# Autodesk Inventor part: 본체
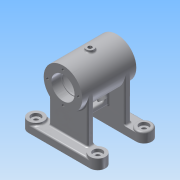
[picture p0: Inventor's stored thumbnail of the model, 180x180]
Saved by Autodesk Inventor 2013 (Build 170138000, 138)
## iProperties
Created: 2015-11
Part Number: 본체
Material: 알루미늄 6061
Document SubType Name: Modeling
Designer: Administrator
Density: 2.71 g/cm^3
Mass: 362.822 g
Surface Area: 463.591 cm^2
Volume: 133.883 cm^3
Author: Administrator
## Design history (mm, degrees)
sketch "스케치1"
  geometry: 1 further point
sketch "스케치2"
  geometry: L1 (0, 40)-(-40, 40); L2 (-40, 40)-(-40, 30); L3 (-40, 20)-(40, 20); L4 (40, 20)-(40, 30); L5 (40, 40)-(0, 40); L6 (0, -40)-(-40, -40); L7 (-40, -40)-(-40, -30); L8 (-40, -20)-(40, -20); L9 (40, -20)-(40, -30); L10 (40, -40)-(0, -40); A1 r 10 centre (-40, 30) between (-40, 40) and (-40, 20); A2 r 10 centre (40, 30) between (40, 20) and (40, 40); A3 r 10 centre (-40, -30) between (-40, -20) and (-40, -40); A4 r 10 centre (40, -30) between (40, -40) and (40, -20)
  constraints: 20 end point, 8 point on circle, 4 centre point, 4 coincident, 2 perpendicular, 2 tangent
  dimensions: "d9" = 40 distance of L1.start L1.end; "d10" = 10 distance of L1.end L2.end; "d11" = 80 distance of L3.start L3.end; "d12" = 10 distance of L3.end L4.end
extrude "돌출1" new body sketch "스케치2" distance "d13" = 10; taper "d14" = 0 deg
node "작업 평면1"
sketch "스케치3"
  geometry: L1 (40, 20)-(-40, 20) reference; L2 (-40, 40)-(40, 40) reference; L3 (-40, -20)-(40, -20) reference; L4 (40, -40)-(-40, -40) reference; C1 r 10 at (-40, 30); A1 r 10 centre (40, 30) between (40, 20) and (40, 40) reference; A2 r 10 centre (-40, 30) between (-40, 40) and (-40, 20) reference; A3 r 10 centre (-40, -30) between (-40, -20) and (-40, -40) reference; A4 r 10 centre (40, -30) between (40, -40) and (40, -20) reference; 4 further points
  constraints: 4 coincident, 3 vertical alignment, 1 centre point, 6 other
  dimensions: "d16" = 20 diameter of C1
extrude "돌출2" join sketch "스케치3" distance "d17" = 3; taper "d18" = 0 deg
sketch "스케치4"
  geometry: L1 (-40, -20)-(40, -20) reference; L2 (40, -40)-(-40, -40) reference; L3 (-40, 40)-(40, 40) reference; L4 (40, 20)-(-40, 20) reference; L5 (0, -20)-(-25, -20); L6 (-25, -20)-(-25, -28); L7 (-25, -28)-(25, -28); L8 (25, -28)-(25, -20); A1 r 10 centre (-40, -30) between (-40, -40) and (-40, -20) reference; A2 r 10 centre (-40, -30) between (-40, -20) and (-40, -40) reference; A3 r 10 centre (40, -30) between (40, -40) and (40, -20) reference; A4 r 10 centre (40, -30) between (40, -20) and (40, -40) reference; A5 r 10 centre (40, 30) between (40, 20) and (40, 40) reference; A6 r 10 centre (40, 30) between (40, 40) and (40, 20) reference; A7 r 10 centre (-40, 30) between (-40, 40) and (-40, 20) reference; A8 r 10 centre (-40, 30) between (-40, 20) and (-40, 40) reference; 1 further point
  constraints: 8 end point, 2 perpendicular, 2 point on line, 1 midpoint, 1 parallel
  dimensions: "d19" = 25 distance of L5.start L5.end; "d20" = 8 distance of L5.end L6.end; "d21" = 50 distance of L6.end L7.end
extrude "돌출3" join sketch "스케치4" distance "d22" = 58; taper "d23" = 0 deg
sketch "스케치5"
  geometry: L1 (0, 0)-(0, 68); C1 r 25 at (0, 68)
  constraints: 2 end point, 1 centre point, 1 coincident, 1 vertical
  dimensions: "d24" = 68 distance of L1.start L1.end; "d25" = 50 diameter of C1
extrude "돌출4" join sketch "스케치5" stored distance "d26" = 70; taper "d27" = 0 deg
node "작업 평면3"
sketch "스케치6"
  geometry: L1 (-25, 28)-(25, 28) reference; L2 (25, 28)-(25, 20) reference; L3 (25, 20)-(-25, 20) reference; L4 (-25, 20)-(-25, 28) reference; L5 (-25, -20)-(25, -20) reference; L6 (25, -20)-(25, -28) reference; L7 (25, -28)-(-25, -28) reference; L8 (-25, -28)-(-25, -20) reference; L9 (-25, 28)-(25, 28) reference; L10 (25, 28)-(25, 20) reference; L11 (25, 20)-(-25, 20) reference; L12 (-25, 20)-(-25, 28) reference; L13 (-25, -20)-(25, -20) reference; L14 (25, -20)-(25, -28) reference; L15 (25, -28)-(-25, -28) reference; L16 (-25, -28)-(-25, -20) reference; L17 (0, 20)-(-4, 20); L18 (-4, 20)-(-4, -20); L19 (-4, -20)-(4, -20); L20 (4, -20)-(4, 20); L21 (4, 20)-(0, 20); 1 further point
  constraints: 10 end point, 4 point on line, 2 perpendicular, 1 collinear, 1 midpoint
  dimensions: "d30" = 8 distance of L18.end L19.end
extrude "돌출5" join sketch "스케치6" stored distance "d31" = 70; taper "d32" = 0 deg
sketch "스케치7"
  geometry: L1 (-13.5, 8.5)-(-13.5, 31.5); L2 (-6.5, 31.5)-(-6.5, 8.5); A1 r 3.5 centre (-10, 31.5) between (-6.5, 31.5) and (-13.5, 31.5); A2 r 3.5 centre (-10, 8.5) between (-13.5, 8.5) and (-6.5, 8.5); 1 further point
  constraints: 4 end point, 4 point on circle, 3 tangent, 2 centre point, 1 parallel
  dimensions: "d35" = 7 diameter of A1; "d37" = 7 diameter of A2
extrude "돌출6" cut sketch "스케치7" distance "d38" = 70; taper "d39" = 0 deg
node "작업 평면7"
sketch "스케치8"
  geometry: C1 r 5 at (0, 0); 1 further point
  constraints: 1 centre point, 1 coincident
  dimensions: "d41" = 10 diameter of C1
extrude "돌출7" join sketch "스케치8" stored distance "d42" = 70; taper "d43" = 0 deg
hole "구멍2" diameter "d55" = 30; stored, may be unused: countersink angle "d59" = 90 deg, drill point angle "d61" = 0 deg; dims "d53" = 10, "d54" = 10, "d56" = 6, "d57" = 4, "d58" = 2, "d60" = 12
hole "구멍3" diameter "d64" = 30; stored, may be unused: countersink angle "d68" = 90 deg, drill point angle "d70" = 0 deg; dims "d62" = 10, "d63" = 10, "d65" = 6, "d66" = 4, "d67" = 2, "d69" = 12
sketch "스케치9"
  geometry: C1 r 14 at (0, 0); 1 further point
  constraints: 1 centre point
  dimensions: "d71" = 28 diameter of C1
extrude "돌출8" cut sketch "스케치9" distance "d72" = 2; taper "d73" = 0 deg
sketch "스케치10"
  geometry: C1 r 14 at (0, 0); 1 further point
  constraints: 1 centre point
  dimensions: "d74" = 28 diameter of C1
extrude "돌출9" cut sketch "스케치10" distance "d75" = 2; taper "d76" = 0 deg
sketch "스케치11"
  geometry: C1 r 21 at (0, 0); 1 further point
  constraints: 1 centre point
  dimensions: "d77" = 42 diameter of C1
extrude "돌출10" cut sketch "스케치11" distance "d78" = 42; taper "d79" = 0 deg
hole "구멍4" diameter "d82" = 4.917; stored, may be unused: countersink angle "d86" = 90 deg, drill point angle "d88" = 0 deg; dims "d80" = 10, "d81" = 10, "d83" = 6, "d84" = 4, "d85" = 2, "d87" = 20
sketch "스케치12"
  geometry: 2 further points
hole "구멍6" sketch "스케치12" at (0, 20) diameter "d102" = 3.242; stored, may be unused: countersink angle "d106" = 82 deg, drill point angle "d108" = 118 deg; dims "d103" = 8, "d104" = 3.023, "d105" = 2, "d107" = 10
node "작업 평면8"
sketch "스케치13"
  geometry: 1 further point
sketch "스케치14"
  geometry: L1 (81.881, 40.033)-(81.881, 16.238); L2 (81.881, 16.238)-(37.794, 16.238); L3 (37.794, 16.238)-(37.794, 40.033); L4 (37.794, 40.033)-(81.881, 40.033); 1 further point
  constraints: 2 other
feature "엠보싱1" sketch "스케치14" dims "d113" = 0.5, "d114" = 0
fillet "모깎기1" dims "d115" = 2
fillet "모깎기2" dims "d116" = 2
fillet "모깎기3" dims "d117" = 2
fillet "모깎기4" dims "d118" = 2
fillet "모깎기5" dims "d119" = 2
hole "구멍7" diameter "d122" = 6; stored, may be unused: countersink angle "d126" = 82 deg, drill point angle "d128" = 0 deg; dims "d120" = 10, "d121" = 10, "d123" = 8, "d124" = 12, "d125" = 4, "d127" = 9
sketch "스케치15"
  geometry: C1 r 3 at (0, 0); 1 further point
  constraints: 1 centre point
  dimensions: "d129" = 6 diameter of C1
extrude "돌출11" cut sketch "스케치15" distance "d130" = 42; taper "d131" = 0 deg
fillet "모깎기6" dims "d132" = 0.3
hole "구멍8" diameter "d141" = 6; stored, may be unused: countersink angle "d145" = 82 deg, drill point angle "d147" = 0 deg; dims "d139" = 10, "d140" = 10, "d142" = 8, "d143" = 12, "d144" = 4, "d146" = 9
hole "구멍9" diameter "d150" = 6; stored, may be unused: countersink angle "d154" = 82 deg, drill point angle "d156" = 0 deg; dims "d148" = 10, "d149" = 10, "d151" = 8, "d152" = 12, "d153" = 4, "d155" = 9
hole "구멍10" diameter "d159" = 6; stored, may be unused: countersink angle "d163" = 82 deg, drill point angle "d165" = 0 deg; dims "d157" = 10, "d158" = 10, "d160" = 8, "d161" = 12, "d162" = 4, "d164" = 9
fillet "모깎기7" dims "d166" = 2
fillet "모깎기9" dims "d168" = 2
fillet "모깎기10" dims "d169" = 2
fillet "모깎기11" dims "d170" = 0.3
node "솔리드1"
mirror "대칭1"
pattern_circular "원형 패턴2" dims angle "d110" = 360 deg
mirror "대칭2"
pattern_linear "직사각형 패턴1" dims "d135" = -80
pattern_linear "직사각형 패턴2"
pattern_circular "원형 패턴3" dims angle "d172" = 360 deg
node "절단 모서리 투영1"
node "절단 모서리 투영2"
node "절단 모서리 투영3"
node "절단 모서리 투영4"
